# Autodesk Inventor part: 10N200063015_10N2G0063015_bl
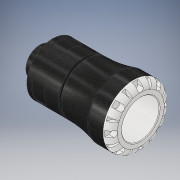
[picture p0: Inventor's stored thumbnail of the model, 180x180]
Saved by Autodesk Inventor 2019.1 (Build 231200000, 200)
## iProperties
Created: 2016-12
Part Number: 10N200063015_10N2G0063015_bl
Material: PVC-Piping
Description: PLASSON MALE ADAPTOR 63X1.1/2" SERIES 1
Document SubType Name: Modeling
Designer: KIM
Mass: 61.7504 g
Surface Area: 140.097 cm^2
Volume: 44.1074 cm^3
Density: 1.4 g/cm^3
Appearance: Black Cast
Author: KIM
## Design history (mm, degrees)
derived "10N20.ipt"
feature "Solid1::10N20.ipt" dims "ScaleForDerivedMember" = 10
tag "TaggingFeature1"
body "Solid1"
other parameters: "d0" = 171 [user parameter], "d1" = 37.38 [user parameter], "d2" = 63 [user parameter], "d3" = 78.75 [user parameter], "d4" = 103 [user parameter], "d6" = 89 [user parameter], "d8" = 87.55 [user parameter], "d13" = 9.7 [user parameter], "d14" = 9.7 [user parameter], "d15" = 0 [user parameter], "d17" = 360 deg [user parameter], "d19" = 8 deg [user parameter], "d20" = 1.26 [user parameter], "d21" = 1.26 [user parameter], "d22" = 8 deg [user parameter], "d24" = 0 [user parameter], "d26" = 360 deg [user parameter], "d32" = 0.925 [user parameter], "d33" = 10.3 [user parameter], "d34" = 47.803 [user parameter], "d35" = 12.6 [user parameter], "d38" = 22 [user parameter], "d39" = 1.43409 [user parameter], "d42" = 22.05 [user parameter], "d43" = 14.49 [user parameter], "d45" = 19.012 [user parameter], "d46" = 0 [user parameter], "d59" = 360 deg [user parameter], "d61" = 18.7425 [user parameter], "d62" = 1.26 [user parameter], "d64" = 0 [user parameter], "d65" = 1.03 [user parameter], "d69" = 2 [user parameter], "d70" = 2.565 [user parameter], "d71" = 3 [user parameter], "d73" = 1 [user parameter], "d_" = 63 [user parameter], "E_" = 103 [user parameter], "H_" = 171 [user parameter], "l_" = 89 [user parameter], "R_" = 47.803 [user parameter], "l_2" = 22 [user parameter], "d9" = 12.125 [user parameter], "d11" = 103 [user parameter], "d12" = 78.75 [user parameter]
